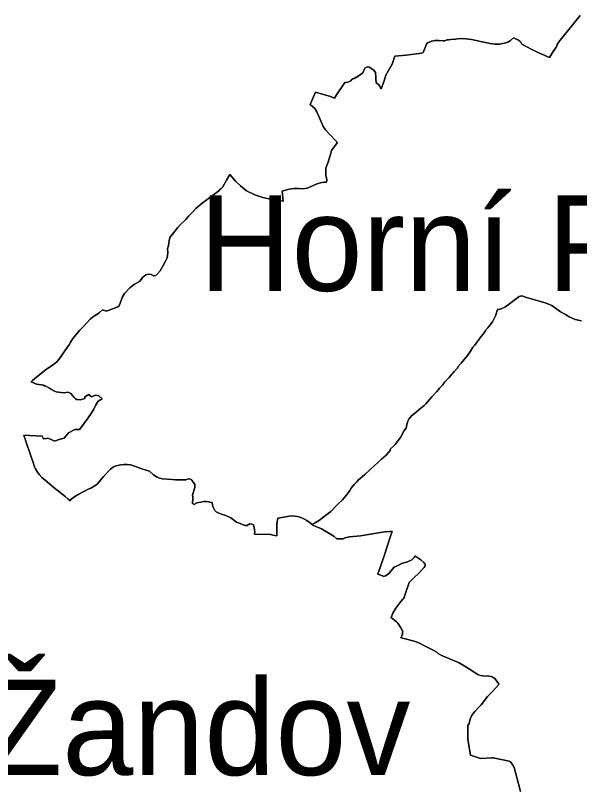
# Model space of a CAD drawing. Extents: x -742239 to -650174, y -1010569 to -945473.
# Drawn here: x -732841 to -729918, y -980134 to -976136 of the extents above; entities that cross this region are included whole.
import ezdxf

# ---------------------------------------------------------------- set-up
doc = ezdxf.new("R2010")
doc.units = 0
doc.layers.add('Hranice obcí', color=7, linetype='Continuous')
doc.layers.add('Obce popis', color=7, linetype='Continuous')

msp = doc.modelspace()

# ---------------------------------------------------------------- linework, layer by layer
at = {"layer": 'Hranice obcí'}
for points in [[(-729914.3, -976136.3), (-730009.3, -976253.8), (-730019.5, -976265.9), (-730033.5, -976287.4), (-730037.1, -976299), (-730042.6, -976305), (-730058.3, -976328.8), (-730074, -976354.1), (-730125.4, -976331.8), (-730165.2, -976312.8), (-730216.1, -976285.5), (-730222, -976275.4), (-730226.8, -976270.3), (-730234.8, -976264.1), (-730260.7, -976251.8), (-730276.3, -976265.3), (-730286.7, -976272.9), (-730299.5, -976278.8), (-730332.6, -976285.6), (-730357, -976285.2), (-730380.4, -976281.5), (-730422.4, -976272.2), (-730478.4, -976261), (-730504.7, -976256.7), (-730528.2, -976256.1), (-730550.1, -976257.3), (-730567.7, -976260.5), (-730578.2, -976259.5), (-730584.6, -976260.2), (-730597.8, -976261.8), (-730604.2, -976262.5), (-730618, -976267.2), (-730624.7, -976267), (-730647.8, -976266.5), (-730661.8, -976266), (-730668.4, -976265.7), (-730684.6, -976270), (-730696.8, -976274.7), (-730706.3, -976278.9), (-730711.3, -976285.3)], [(-730422.4, -976272.2), (-730380.4, -976281.5), (-730357, -976285.2), (-730332.6, -976285.6), (-730299.5, -976278.8), (-730286.7, -976272.9), (-730276.3, -976265.3), (-730260.7, -976251.8), (-730234.8, -976264.1), (-730226.8, -976270.3), (-730222, -976275.4), (-730216.1, -976285.5), (-730165.2, -976312.8), (-730125.4, -976331.8), (-730074, -976354.1), (-730058.3, -976328.8), (-730042.6, -976305), (-730037.1, -976299), (-730033.5, -976287.4), (-730019.5, -976265.9), (-730009.3, -976253.8), (-729914.3, -976136.3)], [(-731920.6, -977152.2), (-731905.4, -977136.2), (-731873.2, -977108.8), (-731822, -977069.5), (-731787.2, -977044.4), (-731780.9, -977036.2), (-731775.6, -977031.7), (-731765.6, -977023.2), (-731747.9, -976988.6), (-731730.8, -976959.1), (-731701, -976995.1), (-731674, -977019.3), (-731642.8, -977044.2), (-731599.8, -977065), (-731558.2, -977079.5), (-731497.2, -977093.4), (-731452.9, -977097.5), (-731459.2, -977045.8), (-731454.5, -977045.3), (-731423.1, -977036.6), (-731399, -977032.8), (-731371.1, -977032.2), (-731351, -977033.5), (-731329.9, -977031.1), (-731305.3, -977020.4), (-731283, -977010.3), (-731272.7, -977007.2), (-731260.9, -977003.7), (-731241, -977000.2), (-731229.2, -977000.1), (-731227.2, -976989), (-731228.3, -976976.8), (-731232, -976965.4), (-731232.2, -976927.6), (-731221.2, -976896.5), (-731206.1, -976849.4), (-731203.9, -976835.9), (-731189.2, -976817), (-731172.8, -976793.6), (-731182.2, -976783.6), (-731211.5, -976752.6), (-731233.6, -976729.2), (-731246.7, -976710.9), (-731250.2, -976702.6), (-731278.5, -976634.6), (-731289.4, -976617.7), (-731313.4, -976597.1), (-731303.8, -976573.7), (-731286.3, -976533), (-731208.3, -976556.1), (-731187, -976564.3), (-731177.2, -976547.4), (-731134.7, -976483.6), (-731119.4, -976481.4), (-731103.8, -976474.1), (-731097.5, -976468.2), (-731093.1, -976464.2), (-731085.7, -976462.1), (-731065.1, -976450.7), (-731040.4, -976433.3), (-731030.3, -976408.9), (-731017.7, -976403.2), (-731007.7, -976404.2), (-730984.2, -976420.3), (-730975.2, -976431.7), (-730972.8, -976455.4), (-730973.9, -976463.6), (-730971.1, -976484.9), (-730966, -976489), (-730959.5, -976494.3), (-730952.8, -976502), (-730948.2, -976517), (-730942, -976507.4), (-730931.7, -976479.7), (-730920.9, -976446.2), (-730889.3, -976388.4), (-730875.4, -976347.2), (-730816.6, -976342), (-730791, -976339), (-730749.1, -976334.2), (-730737, -976331.3), (-730728.4, -976328), (-730711.3, -976285.3), (-730706.3, -976278.9), (-730696.8, -976274.7), (-730684.6, -976270), (-730668.4, -976265.7), (-730661.8, -976266), (-730647.8, -976266.5), (-730624.7, -976267), (-730618, -976267.2), (-730604.2, -976262.5), (-730597.8, -976261.8), (-730584.6, -976260.2), (-730578.2, -976259.5), (-730567.7, -976260.5), (-730550.1, -976257.3), (-730528.2, -976256.1), (-730504.7, -976256.7), (-730478.4, -976261), (-730422.4, -976272.2)], [(-730711.3, -976285.3), (-730728.4, -976328), (-730737, -976331.3), (-730749.1, -976334.2), (-730791, -976339), (-730816.6, -976342), (-730875.4, -976347.2), (-730889.3, -976388.4), (-730920.9, -976446.2), (-730931.7, -976479.7), (-730942, -976507.4), (-730948.2, -976517), (-730952.8, -976502), (-730959.5, -976494.3), (-730966, -976489), (-730971.1, -976484.9), (-730973.9, -976463.6), (-730972.8, -976455.4), (-730975.2, -976431.7), (-730984.2, -976420.3), (-731007.7, -976404.2), (-731017.7, -976403.2), (-731030.3, -976408.9), (-731040.4, -976433.3), (-731065.1, -976450.7), (-731085.7, -976462.1), (-731093.1, -976464.2), (-731097.5, -976468.2), (-731103.8, -976474.1), (-731119.4, -976481.4), (-731134.7, -976483.6), (-731177.2, -976547.4), (-731187, -976564.3), (-731208.3, -976556.1), (-731286.3, -976533), (-731303.8, -976573.7), (-731313.4, -976597.1), (-731289.4, -976617.7), (-731278.5, -976634.6), (-731250.2, -976702.6), (-731246.7, -976710.9), (-731233.6, -976729.2), (-731211.5, -976752.6), (-731182.2, -976783.6), (-731172.8, -976793.6), (-731189.2, -976817), (-731203.9, -976835.9), (-731206.1, -976849.4), (-731221.2, -976896.5), (-731232.2, -976927.6), (-731232, -976965.4), (-731228.3, -976976.8), (-731227.2, -976989), (-731229.2, -977000.1), (-731241, -977000.2), (-731260.9, -977003.7), (-731272.7, -977007.2), (-731283, -977010.3), (-731305.3, -977020.4), (-731329.9, -977031.1), (-731351, -977033.5), (-731371.1, -977032.2), (-731399, -977032.8), (-731423.1, -977036.6), (-731454.5, -977045.3), (-731459.2, -977045.8), (-731452.9, -977097.5), (-731497.2, -977093.4), (-731558.2, -977079.5), (-731599.8, -977065), (-731642.8, -977044.2), (-731674, -977019.3), (-731701, -976995.1), (-731730.8, -976959.1), (-731747.9, -976988.6), (-731765.6, -977023.2), (-731775.6, -977031.7), (-731780.9, -977036.2), (-731787.2, -977044.4), (-731822, -977069.5), (-731873.2, -977108.8), (-731905.4, -977136.2), (-731920.6, -977152.2), (-731944.2, -977175.2), (-731957.6, -977192.8), (-731985.9, -977219.5), (-731999.4, -977234.5), (-732040.1, -977285.9), (-732043.6, -977304.1), (-732047.4, -977327), (-732052.3, -977345.4), (-732051.9, -977365.1), (-732054.7, -977391.1), (-732063.4, -977409.3), (-732076.2, -977430.7), (-732091.4, -977458.1), (-732104.3, -977474.7), (-732114.3, -977483.4), (-732123.7, -977484.4), (-732138.2, -977477.8), (-732151.3, -977475.7)], [(-732687, -978542.9), (-732702, -978529.7), (-732715.6, -978515.3), (-732726.6, -978501), (-732737.5, -978483.6), (-732741.6, -978473.9), (-732751.6, -978445.6), (-732762.4, -978411.1), (-732785.2, -978345.2), (-732796.7, -978309.1), (-732701.6, -978314.1), (-732696.1, -978329.4), (-732679.4, -978327.2), (-732672.8, -978325.7), (-732668.3, -978326.7), (-732636.1, -978341.1), (-732615.3, -978332.8), (-732588.6, -978325.9), (-732566.1, -978298), (-732534, -978279.4), (-732508.6, -978280), (-732480.6, -978243.6), (-732451.8, -978202.2), (-732435, -978175.5), (-732424.4, -978152.3), (-732413.1, -978134.1), (-732391.6, -978121.3), (-732409.6, -978105.3), (-732424.4, -978102.7), (-732446.1, -978111.8), (-732460.9, -978099.6), (-732481.3, -978111.8), (-732481.3, -978119.9), (-732503.1, -978127.1), (-732523.5, -978125.7), (-732531.7, -978120.4), (-732538.4, -978112.4), (-732544.4, -978105.5), (-732554.7, -978094.3), (-732569.8, -978086.6), (-732588.2, -978089.6), (-732606.3, -978089.1), (-732629.1, -978085.3), (-732639, -978081.4), (-732654.1, -978073.1), (-732665, -978065.8), (-732683, -978056), (-732690.8, -978053.4), (-732694.8, -978051), (-732707.8, -978049.6), (-732732.1, -978045.4), (-732759.6, -978033.4), (-732752.8, -978025.7), (-732729.5, -978007), (-732679.2, -977968.2), (-732655.5, -977953), (-732627.6, -977931.3), (-732615.3, -977918.6), (-732561.2, -977837.6), (-732556.9, -977831), (-732546.6, -977815.1), (-732535.8, -977800.2), (-732509.2, -977767.7), (-732490.4, -977749), (-732453.3, -977708.7), (-732441, -977698.6), (-732437.2, -977695.9), (-732430.6, -977692), (-732413.2, -977681.9), (-732406.2, -977674.9), (-732390.1, -977661.2), (-732368.3, -977667.2), (-732309.9, -977645.8), (-732303.7, -977639.2), (-732286.7, -977592.8), (-732276, -977575.2), (-732248.9, -977547.5), (-732223.6, -977528.1), (-732198.3, -977513.6), (-732187.4, -977501.6), (-732182.9, -977493.3), (-732164.5, -977480.2), (-732151.3, -977475.7), (-732138.2, -977477.8), (-732123.7, -977484.4), (-732114.3, -977483.4), (-732104.3, -977474.7), (-732091.4, -977458.1), (-732076.2, -977430.7), (-732063.4, -977409.3), (-732054.7, -977391.1), (-732051.9, -977365.1), (-732052.3, -977345.4), (-732047.4, -977327), (-732043.6, -977304.1), (-732040.1, -977285.9), (-731999.4, -977234.5), (-731985.9, -977219.5), (-731957.6, -977192.8), (-731944.2, -977175.2), (-731920.6, -977152.2)], [(-732151.3, -977475.7), (-732164.5, -977480.2), (-732182.9, -977493.3), (-732187.4, -977501.6), (-732198.3, -977513.6), (-732223.6, -977528.1), (-732248.9, -977547.5), (-732276, -977575.2), (-732286.7, -977592.8), (-732303.7, -977639.2), (-732309.9, -977645.8), (-732368.3, -977667.2), (-732390.1, -977661.2), (-732406.2, -977674.9), (-732413.2, -977681.9), (-732430.6, -977692), (-732437.2, -977695.9), (-732441, -977698.6), (-732453.3, -977708.7), (-732490.4, -977749), (-732509.2, -977767.7), (-732535.8, -977800.2), (-732546.6, -977815.1), (-732556.9, -977831), (-732561.2, -977837.6), (-732615.3, -977918.6), (-732627.6, -977931.3), (-732655.5, -977953), (-732679.2, -977968.2), (-732729.5, -978007), (-732752.8, -978025.7), (-732759.6, -978033.4), (-732732.1, -978045.4), (-732707.8, -978049.6), (-732694.8, -978051), (-732690.8, -978053.4), (-732683, -978056), (-732665, -978065.8), (-732654.1, -978073.1), (-732639, -978081.4), (-732629.1, -978085.3), (-732606.3, -978089.1), (-732588.2, -978089.6), (-732569.8, -978086.6), (-732554.7, -978094.3), (-732544.4, -978105.5), (-732538.4, -978112.4), (-732531.7, -978120.4), (-732523.5, -978125.7), (-732503.1, -978127.1), (-732481.3, -978119.9), (-732481.3, -978111.8), (-732460.9, -978099.6), (-732446.1, -978111.8), (-732424.4, -978102.7), (-732409.6, -978105.3), (-732391.6, -978121.3), (-732413.1, -978134.1), (-732424.4, -978152.3), (-732435, -978175.5), (-732451.8, -978202.2), (-732480.6, -978243.6), (-732508.6, -978280), (-732534, -978279.4), (-732566.1, -978298), (-732588.6, -978325.9), (-732615.3, -978332.8), (-732636.1, -978341.1), (-732668.3, -978326.7), (-732672.8, -978325.7), (-732679.4, -978327.2), (-732696.1, -978329.4), (-732701.6, -978314.1), (-732796.7, -978309.1), (-732785.2, -978345.2), (-732762.4, -978411.1), (-732751.6, -978445.6), (-732741.6, -978473.9), (-732737.5, -978483.6), (-732726.6, -978501), (-732715.6, -978515.3), (-732702, -978529.7), (-732687, -978542.9), (-732640.2, -978581.8), (-732585.3, -978624.7), (-732568.5, -978640.8), (-732562.1, -978644.4), (-732558.4, -978649.5), (-732552, -978641.8), (-732540.8, -978631.8), (-732532.9, -978626.4), (-732512.5, -978614.5), (-732464, -978589.4), (-732450, -978583.4), (-732423.6, -978569), (-732415.9, -978561.1), (-732385.1, -978524.2), (-732347.7, -978484.9), (-732338.7, -978477.5), (-732335.2, -978475.5), (-732329.1, -978471.8)], [(-731110.3, -978836.5), (-731132, -978841.2), (-731142.7, -978846.9), (-731175, -978846.6), (-731191.7, -978831.8), (-731255.1, -978794.7), (-731288.6, -978781.2), (-731296.2, -978777.6), (-731303.8, -978772.4), (-731291.8, -978765.2), (-731265.3, -978749.5), (-731233.6, -978725.8), (-731207.4, -978704.9), (-731176, -978672.9), (-731171.6, -978667.9), (-731146.2, -978644.9), (-731128.8, -978623.9), (-731114.9, -978605.9), (-731107.7, -978595.5), (-731101.3, -978584.2), (-731085.9, -978565.9), (-731071.8, -978552.1), (-731062.7, -978541.6), (-731052.7, -978531.8), (-731030.8, -978514.1), (-730982.1, -978468.3), (-730944.9, -978433.5), (-730920.5, -978412.6), (-730899.3, -978389.3), (-730896.8, -978380.3), (-730882.6, -978366), (-730873.2, -978358.6), (-730857.4, -978337), (-730846.4, -978322), (-730826.8, -978285.1), (-730816.2, -978273.9), (-730812.3, -978254.9), (-730807.6, -978237.2), (-730801.7, -978226.7), (-730788.3, -978210.1), (-730773.2, -978197.3), (-730740.8, -978170.1), (-730723.5, -978155.5), (-730715.1, -978147.3), (-730682.8, -978111.4), (-730675.5, -978102.8), (-730659.6, -978085), (-730647.8, -978072.2), (-730643.6, -978067), (-730636.1, -978058.9), (-730627.8, -978049.9), (-730615.4, -978034.1), (-730594.2, -978011.5), (-730579.7, -977994.3), (-730574.2, -977988.6), (-730567.1, -977979.9), (-730550.9, -977961.9), (-730546, -977954.6), (-730531.2, -977937.1), (-730499, -977897.1), (-730483.4, -977874.5), (-730470.1, -977854.7), (-730462, -977845), (-730436.7, -977810.3), (-730434.2, -977806.9), (-730428.6, -977800.2), (-730417.4, -977785.9), (-730414, -977780.9), (-730411.2, -977777), (-730405.8, -977770), (-730401, -977763.2), (-730393.8, -977754.5), (-730381.7, -977738.5), (-730369.2, -977723.4), (-730363.4, -977711.6), (-730353.9, -977691.9), (-730347.4, -977675.7), (-730344.3, -977662.9), (-730343.2, -977658.4), (-730338.1, -977659.1), (-730323.4, -977655.9), (-730302.3, -977645.2), (-730231.6, -977591.1), (-730216.8, -977588.7), (-730192.3, -977597.5), (-730119.7, -977617), (-730090.4, -977626.1), (-730062.2, -977637.5), (-730016.8, -977670.2), (-729991.1, -977684.7), (-729971.3, -977697), (-729940.6, -977710), (-729907.6, -977717.4)], [(-729907.6, -977717.4), (-729940.6, -977710), (-729971.3, -977697), (-729991.1, -977684.7), (-730016.8, -977670.2), (-730062.2, -977637.5), (-730090.4, -977626.1), (-730119.7, -977617), (-730192.3, -977597.5), (-730216.8, -977588.7), (-730231.6, -977591.1), (-730302.3, -977645.2), (-730323.4, -977655.9), (-730338.1, -977659.1), (-730343.2, -977658.4), (-730344.3, -977662.9), (-730347.4, -977675.7), (-730353.9, -977691.9), (-730363.4, -977711.6), (-730369.2, -977723.4), (-730381.7, -977738.5), (-730393.8, -977754.5), (-730401, -977763.2), (-730405.8, -977770), (-730411.2, -977777), (-730414, -977780.9), (-730417.4, -977785.9), (-730428.6, -977800.2), (-730434.2, -977806.9), (-730436.7, -977810.3), (-730462, -977845), (-730470.1, -977854.7), (-730483.4, -977874.5)], [(-730483.4, -977874.5), (-730499, -977897.1), (-730531.2, -977937.1), (-730546, -977954.6), (-730550.9, -977961.9), (-730567.1, -977979.9), (-730574.2, -977988.6), (-730579.7, -977994.3), (-730594.2, -978011.5), (-730615.4, -978034.1), (-730627.8, -978049.9), (-730636.1, -978058.9), (-730643.6, -978067), (-730647.8, -978072.2), (-730659.6, -978085), (-730675.5, -978102.8), (-730682.8, -978111.4), (-730715.1, -978147.3), (-730723.5, -978155.5), (-730740.8, -978170.1), (-730773.2, -978197.3), (-730788.3, -978210.1), (-730801.7, -978226.7), (-730807.6, -978237.2), (-730812.3, -978254.9), (-730816.2, -978273.9), (-730826.8, -978285.1), (-730846.4, -978322), (-730857.4, -978337), (-730873.2, -978358.6), (-730882.6, -978366), (-730896.8, -978380.3), (-730899.3, -978389.3), (-730920.5, -978412.6), (-730944.9, -978433.5), (-730982.1, -978468.3), (-731030.8, -978514.1), (-731052.7, -978531.8), (-731062.7, -978541.6), (-731071.8, -978552.1), (-731085.9, -978565.9), (-731101.3, -978584.2), (-731107.7, -978595.5), (-731114.9, -978605.9), (-731128.8, -978623.9), (-731146.2, -978644.9), (-731171.6, -978667.9), (-731176, -978672.9), (-731207.4, -978704.9), (-731233.6, -978725.8), (-731265.3, -978749.5), (-731291.8, -978765.2), (-731303.8, -978772.4)], [(-731303.8, -978772.4), (-731314.2, -978763.7), (-731330.2, -978752.1), (-731346.9, -978742.1), (-731362.8, -978735.5), (-731379.3, -978730.4), (-731392.7, -978728.3), (-731404.8, -978728), (-731420.9, -978729.5), (-731481.7, -978739.8), (-731483.3, -978749.9), (-731484.2, -978756), (-731486.6, -978772.5), (-731486.2, -978782.8), (-731486.8, -978789.1), (-731486.8, -978830.8), (-731507.1, -978827.8), (-731512.5, -978825.3), (-731517.2, -978824.2), (-731533.2, -978822.8), (-731552.1, -978824.1), (-731602.9, -978822.2), (-731601.4, -978817.8), (-731600.6, -978812.3), (-731601.6, -978797.9), (-731604.1, -978789.5), (-731607.5, -978773.6), (-731616.1, -978770.1), (-731627.9, -978768.2), (-731640.8, -978778.1), (-731651.8, -978777.7), (-731676.9, -978767.6), (-731695.1, -978759.3), (-731711.2, -978747.2), (-731724.2, -978738.5), (-731750.6, -978726.3), (-731772.6, -978718.2), (-731781.2, -978715.6), (-731790.7, -978711.2), (-731800.1, -978705.9), (-731807.6, -978699.2), (-731814.5, -978686.2), (-731819.5, -978672.1), (-731821.3, -978658.1), (-731833, -978657), (-731839, -978655.3), (-731852.5, -978653.7), (-731865.3, -978653.4), (-731880, -978655.7), (-731901.3, -978660.1), (-731908.6, -978662.9), (-731913.2, -978668.2), (-731923.9, -978663.1), (-731924.1, -978656.1), (-731921.6, -978644.6), (-731920.9, -978634.6), (-731922.3, -978628.4), (-731922.7, -978620.2), (-731911.1, -978580.6), (-731911.8, -978564.5), (-731926.9, -978543), (-731930.4, -978539.1), (-731938.1, -978535.7), (-731947.4, -978537.3), (-731957.9, -978541.1), (-731962.3, -978541.7), (-731988.4, -978540.9), (-731992.3, -978540.7), (-732011.3, -978541.4), (-732029.2, -978539.6), (-732079.6, -978536.3), (-732093, -978532.9), (-732105.8, -978526.5), (-732125.4, -978515.3), (-732145.9, -978495.4), (-732180.2, -978485.1), (-732223.6, -978469.4), (-732245.2, -978463.7), (-732261.4, -978461.4), (-732279, -978461), (-732295.6, -978462.8), (-732318.3, -978467.6), (-732329.1, -978471.8), (-732335.2, -978475.5), (-732338.7, -978477.5), (-732347.7, -978484.9), (-732385.1, -978524.2), (-732415.9, -978561.1), (-732423.6, -978569), (-732450, -978583.4), (-732464, -978589.4), (-732512.5, -978614.5), (-732532.9, -978626.4), (-732540.8, -978631.8), (-732552, -978641.8), (-732558.4, -978649.5), (-732562.1, -978644.4), (-732568.5, -978640.8), (-732585.3, -978624.7), (-732640.2, -978581.8), (-732687, -978542.9)], [(-732329.1, -978471.8), (-732318.3, -978467.6), (-732295.6, -978462.8), (-732279, -978461), (-732261.4, -978461.4), (-732245.2, -978463.7), (-732223.6, -978469.4), (-732180.2, -978485.1), (-732145.9, -978495.4), (-732125.4, -978515.3), (-732105.8, -978526.5), (-732093, -978532.9), (-732079.6, -978536.3), (-732029.2, -978539.6), (-732011.3, -978541.4), (-731992.3, -978540.7), (-731988.4, -978540.9), (-731962.3, -978541.7), (-731957.9, -978541.1), (-731947.4, -978537.3), (-731938.1, -978535.7), (-731930.4, -978539.1), (-731926.9, -978543), (-731911.8, -978564.5), (-731911.1, -978580.6), (-731922.7, -978620.2), (-731922.3, -978628.4), (-731920.9, -978634.6), (-731921.6, -978644.6), (-731924.1, -978656.1), (-731923.9, -978663.1), (-731913.2, -978668.2), (-731908.6, -978662.9), (-731901.3, -978660.1), (-731880, -978655.7), (-731865.3, -978653.4), (-731852.5, -978653.7), (-731839, -978655.3), (-731833, -978657), (-731821.3, -978658.1), (-731819.5, -978672.1), (-731814.5, -978686.2), (-731807.6, -978699.2), (-731800.1, -978705.9), (-731790.7, -978711.2), (-731781.2, -978715.6), (-731772.6, -978718.2), (-731750.6, -978726.3), (-731724.2, -978738.5), (-731711.2, -978747.2), (-731695.1, -978759.3), (-731676.9, -978767.6), (-731651.8, -978777.7), (-731640.8, -978778.1), (-731627.9, -978768.2), (-731616.1, -978770.1), (-731607.5, -978773.6), (-731604.1, -978789.5), (-731601.6, -978797.9), (-731600.6, -978812.3), (-731601.4, -978817.8), (-731602.9, -978822.2), (-731552.1, -978824.1), (-731533.2, -978822.8), (-731517.2, -978824.2), (-731512.5, -978825.3), (-731507.1, -978827.8), (-731486.8, -978830.8), (-731486.8, -978789.1), (-731486.2, -978782.8), (-731486.6, -978772.5), (-731484.2, -978756), (-731483.3, -978749.9), (-731481.7, -978739.8), (-731420.9, -978729.5), (-731404.8, -978728), (-731392.7, -978728.3), (-731379.3, -978730.4), (-731362.8, -978735.5), (-731346.9, -978742.1), (-731330.2, -978752.1), (-731314.2, -978763.7), (-731303.8, -978772.4), (-731296.2, -978777.6), (-731288.6, -978781.2), (-731255.1, -978794.7), (-731191.7, -978831.8), (-731175, -978846.6), (-731142.7, -978846.9), (-731132, -978841.2), (-731110.3, -978836.5), (-731053.3, -978830), (-731022, -978825.9), (-730928, -978810.7), (-730901.8, -978807.9), (-730888.4, -978808.7), (-730901, -978843.3), (-730929.1, -978929.7), (-730949.6, -978989.4), (-730962.8, -979028.9), (-730938.8, -979038.2)], [(-730224.6, -980154.3), (-730234.3, -980114.3), (-730257, -980030.8), (-730263.3, -980018.4), (-730276.4, -980001.8), (-730282.7, -979996.8), (-730366, -979980.9), (-730371.1, -979980.6), (-730430.5, -979984.1), (-730483, -979965.8), (-730495.7, -979895.5), (-730496.5, -979880), (-730497, -979812.1), (-730490.6, -979802.8), (-730482.2, -979773.2), (-730476.9, -979761.4), (-730470.9, -979752.9), (-730461, -979741.3), (-730439.8, -979718.7), (-730427.1, -979706.7), (-730395.2, -979662.1), (-730370.8, -979638.9), (-730336.2, -979599.8), (-730338.3, -979595.7), (-730357.3, -979570.1), (-730365.4, -979564.2), (-730371.1, -979561), (-730376.7, -979559.6), (-730388, -979558), (-730419.1, -979556.2), (-730430.4, -979553.3), (-730439.4, -979549.9), (-730444.8, -979548.6), (-730507, -979509.3), (-730545.3, -979486.9), (-730625.1, -979454.5), (-730648.6, -979442.5), (-730658.1, -979432.9), (-730673.5, -979424.5), (-730725.5, -979399.2), (-730739.9, -979390.2), (-730758.8, -979382), (-730775.6, -979376), (-730821.8, -979365), (-730843.9, -979358.7), (-730838.4, -979349.4), (-730835.7, -979340.4), (-730834.5, -979333.4), (-730833.3, -979326.6), (-730843.2, -979307.2), (-730859.6, -979282.4), (-730867, -979276.3), (-730894.4, -979254.2), (-730884.8, -979231.9), (-730870.1, -979204.8), (-730843.5, -979171.1), (-730833.3, -979158.7), (-730830.9, -979155.1), (-730827.4, -979149.8), (-730821.7, -979133.4), (-730805, -979082.4), (-730800.1, -979073.2), (-730778.3, -979050.8), (-730747.4, -979020.8), (-730733.7, -979005.7), (-730723.4, -978994.2), (-730720.1, -978989.7), (-730718, -978984.1), (-730717.5, -978979.6), (-730719.3, -978975.1), (-730724.4, -978968.8), (-730739.8, -978955.1), (-730760.2, -978940.6), (-730768.6, -978934.4), (-730774.9, -978942.8), (-730780.3, -978948.6), (-730787.6, -978954.7), (-730794, -978958.5), (-730810.2, -978965.2), (-730838.9, -978974.9), (-730866.8, -978987.4), (-730878.2, -978993.7), (-730906.2, -979025.3), (-730920.8, -979036.1), (-730931.8, -979041.1), (-730938.8, -979038.2), (-730962.8, -979028.9), (-730949.6, -978989.4), (-730929.1, -978929.7), (-730901, -978843.3), (-730888.4, -978808.7), (-730901.8, -978807.9), (-730928, -978810.7), (-731022, -978825.9), (-731053.3, -978830), (-731110.3, -978836.5)], [(-730938.8, -979038.2), (-730931.8, -979041.1), (-730920.8, -979036.1), (-730906.2, -979025.3), (-730878.2, -978993.7), (-730866.8, -978987.4), (-730838.9, -978974.9), (-730810.2, -978965.2), (-730794, -978958.5), (-730787.6, -978954.7), (-730780.3, -978948.6), (-730774.9, -978942.8), (-730768.6, -978934.4), (-730760.2, -978940.6), (-730739.8, -978955.1), (-730724.4, -978968.8), (-730719.3, -978975.1), (-730717.5, -978979.6), (-730718, -978984.1), (-730720.1, -978989.7), (-730723.4, -978994.2), (-730733.7, -979005.7), (-730747.4, -979020.8), (-730778.3, -979050.8), (-730800.1, -979073.2), (-730805, -979082.4), (-730821.7, -979133.4), (-730827.4, -979149.8), (-730830.9, -979155.1), (-730833.3, -979158.7), (-730843.5, -979171.1), (-730870.1, -979204.8), (-730884.8, -979231.9), (-730894.4, -979254.2), (-730867, -979276.3), (-730859.6, -979282.4), (-730843.2, -979307.2), (-730833.3, -979326.6), (-730834.5, -979333.4), (-730835.7, -979340.4), (-730838.4, -979349.4), (-730843.9, -979358.7), (-730821.8, -979365), (-730775.6, -979376), (-730758.8, -979382), (-730739.9, -979390.2), (-730725.5, -979399.2), (-730673.5, -979424.5), (-730658.1, -979432.9), (-730648.6, -979442.5), (-730625.1, -979454.5), (-730545.3, -979486.9), (-730507, -979509.3), (-730444.8, -979548.6), (-730439.4, -979549.9), (-730430.4, -979553.3), (-730419.1, -979556.2), (-730388, -979558), (-730376.7, -979559.6), (-730371.1, -979561), (-730365.4, -979564.2), (-730357.3, -979570.1), (-730338.3, -979595.7), (-730336.2, -979599.8), (-730370.8, -979638.9), (-730395.2, -979662.1), (-730427.1, -979706.7), (-730439.8, -979718.7), (-730461, -979741.3), (-730470.9, -979752.9), (-730476.9, -979761.4), (-730482.2, -979773.2), (-730490.6, -979802.8), (-730497, -979812.1), (-730496.5, -979880), (-730495.7, -979895.5), (-730483, -979965.8), (-730430.5, -979984.1), (-730371.1, -979980.6), (-730366, -979980.9), (-730282.7, -979996.8), (-730276.4, -980001.8), (-730263.3, -980018.4), (-730257, -980030.8), (-730234.3, -980114.3), (-730224.6, -980154.3)]]:
    msp.add_lwpolyline(points, dxfattribs=at)

# ---------------------------------------------------------------- texts
at = {"layer": 'Obce popis'}
for s, p in [('Horní Police', (-731888.1, -977562.4)), ('Žandov', (-733002.5, -980069.8))]:
    msp.add_text(s, height=495, dxfattribs=at).set_placement(p)

doc.saveas('drawing.dxf')
